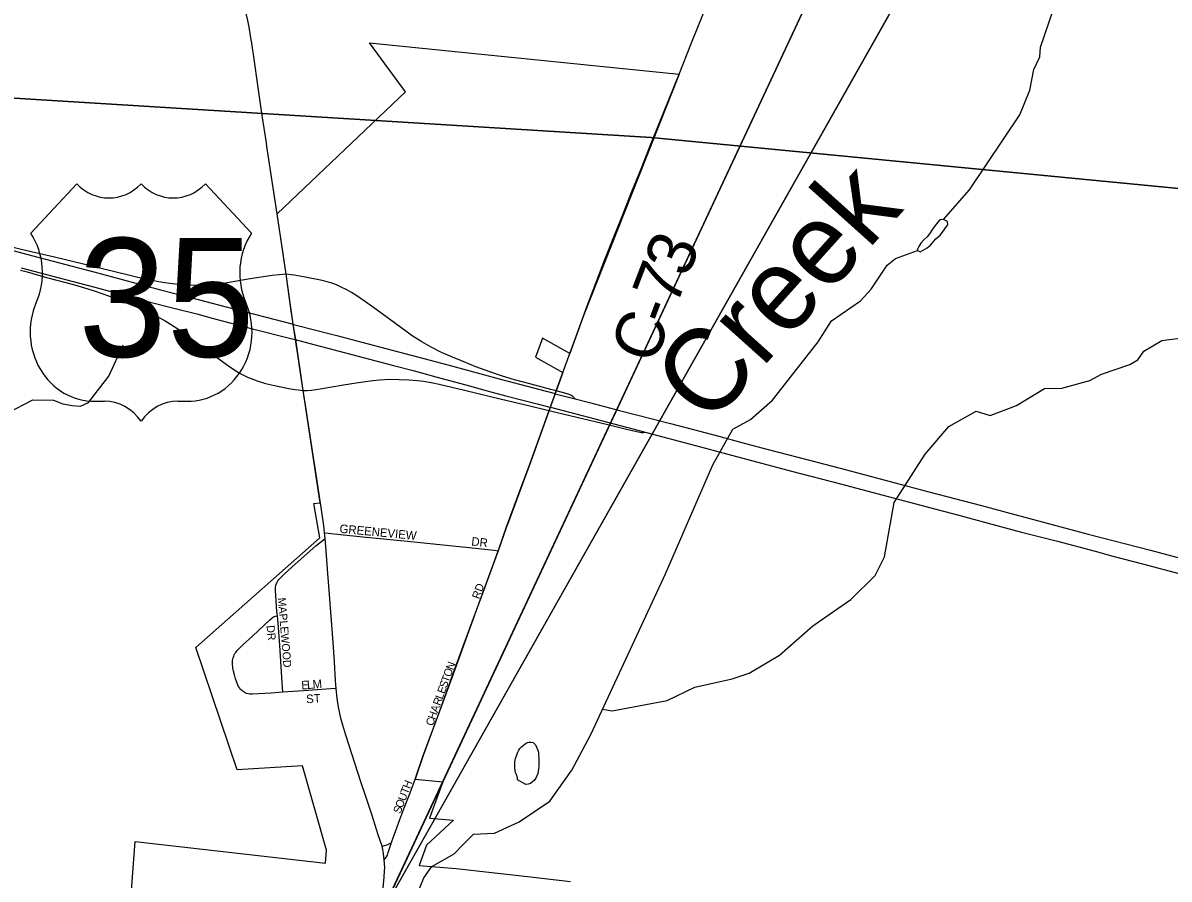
# Model space of a CAD drawing. Extents: x -13.9 to 69.1, y -25.2 to 26.1.
# Drawn here: x 3.861 to 5.08, y 17.993 to 18.903 of the extents above; entities that cross this region are included whole.
import ezdxf

# ---------------------------------------------------------------- set-up
doc = ezdxf.new("R2010")
doc.units = 0
for name, color, linetype in [('GM_X_City_Street', 7, 'Continuous'), ('GM_X_City_Street_Text', 7, 'Continuous'), ('GM_X_Corporation', 7, 'Continuous'), ('GM_X_County_Road', 7, 'Continuous'), ('GM_X_County_Road_Text', 7, 'Continuous'), ('GM_X_Interchange_Ramps', 7, 'Continuous'), ('GM_X_Major_River', 7, 'Continuous'), ('GM_X_Major_River_Text', 7, 'Continuous'), ('GM_X_Minor_Lake', 7, 'Continuous'), ('GM_X_Minor_River', 7, 'Continuous'), ('GM_X_State_Route', 7, 'Continuous'), ('GM_X_Township', 7, 'Continuous'), ('GM_X_US_Location', 7, 'Continuous'), ('GM_X_US_Route', 7, 'Continuous'), ('GM_X_US_Shield', 7, 'Continuous'), ('SH_Text', 7, 'Continuous')]:
    doc.layers.add(name, color=color, linetype=linetype)

msp = doc.modelspace()

# ---------------------------------------------------------------- linework, layer by layer
at = {"layer": 'GM_X_City_Street'}
for points in [[(4.1814, 18.3613), (4.1853, 18.3609), (4.2018, 18.3591), (4.2222, 18.357), (4.244, 18.3548), (4.2732, 18.3519), (4.3042, 18.3488), (4.3352, 18.3457), (4.3552, 18.3437), (4.3582, 18.3433), (4.3623, 18.3428), (4.3662, 18.3423)], [(4.3662, 18.3423), (4.3663, 18.3427), (4.3751, 18.3675)], [(4.1313, 18.2731), (4.1308, 18.2777), (4.1295, 18.2942), (4.1294, 18.3004), (4.1294, 18.3026), (4.1294, 18.304), (4.1296, 18.3051), (4.1301, 18.3065), (4.1308, 18.3081), (4.1314, 18.3094), (4.1319, 18.3102), (4.1329, 18.3115), (4.134, 18.3128), (4.1389, 18.3177), (4.1503, 18.328), (4.1723, 18.3476), (4.182, 18.3553)], [(4.3602, 18.3253), (4.3612, 18.3282), (4.3662, 18.3423)], [(4.2557, 18.0409), (4.2615, 18.0564), (4.2658, 18.0679), (4.2725, 18.0848), (4.2779, 18.0993), (4.2864, 18.1244), (4.3011, 18.1642), (4.318, 18.2106), (4.329, 18.2409), (4.3454, 18.2857), (4.3602, 18.3253)], [(4.1372, 18.1917), (4.1246, 18.1909), (4.1114, 18.19), (4.1044, 18.1897), (4.1022, 18.1898), (4.1003, 18.1901), (4.0986, 18.1906), (4.0972, 18.1912), (4.096, 18.1919), (4.0948, 18.1926), (4.0932, 18.194), (4.092, 18.1951), (4.091, 18.1964), (4.09, 18.198), (4.0892, 18.1998), (4.0885, 18.2014), (4.0869, 18.2061), (4.0857, 18.2101), (4.0846, 18.2143), (4.0843, 18.2155), (4.0839, 18.2172), (4.0838, 18.2187), (4.0836, 18.2209), (4.0836, 18.2231), (4.0837, 18.2255), (4.084, 18.227), (4.0843, 18.2284), (4.0849, 18.2302), (4.0855, 18.2316), (4.0862, 18.2329), (4.0871, 18.2342), (4.0883, 18.2358), (4.0897, 18.2373), (4.0946, 18.242), (4.1048, 18.2513), (4.1234, 18.2686), (4.1254, 18.2704), (4.1262, 18.2711), (4.1273, 18.2718), (4.1283, 18.2723), (4.1293, 18.2726), (4.1306, 18.273), (4.1313, 18.2731)], [(4.1372, 18.1917), (4.136, 18.2074), (4.1339, 18.2417), (4.132, 18.2653), (4.1313, 18.2731)], [(4.1939, 18.1959), (4.1929, 18.1958), (4.1736, 18.1945), (4.1592, 18.1934), (4.1425, 18.1921), (4.1372, 18.1917)], [(4.2527, 18.0319), (4.2551, 18.0391), (4.2557, 18.0409)], [(4.2427, 18.0281), (4.2465, 18.0292), (4.2487, 18.0299), (4.2508, 18.031), (4.2527, 18.0319)], [(4.245, 18.0134), (4.2474, 18.0169), (4.2484, 18.0186), (4.2493, 18.0212), (4.2527, 18.0319)]]:
    msp.add_lwpolyline(points, dxfattribs=at)
at = {"layer": 'GM_X_Corporation'}
msp.add_lwpolyline([(3.9756, 17.9719), (3.9802, 18.0329), (4.1826, 18.01), (4.1837, 18.024), (4.1579, 18.1136), (4.0885, 18.1093), (4.0447, 18.2393), (4.1764, 18.3558), (4.1701, 18.3926), (4.1767, 18.3932), (4.1588, 18.5125), (4.1508, 18.5667), (4.1482, 18.5832), (4.1405, 18.6363), (4.131, 18.7004), (4.2677, 18.8302), (4.2293, 18.8824), (4.5587, 18.8488), (4.4573, 18.5931), (4.4422, 18.5518), (4.4132, 18.5682), (4.4059, 18.5479), (4.4349, 18.5318), (4.4279, 18.5123), (4.4, 18.4353), (4.3771, 18.3731), (4.3751, 18.3675), (4.3662, 18.3423), (4.3496, 18.2969), (4.3439, 18.2816), (4.3167, 18.2071), (4.2864, 18.1244), (4.2779, 18.0993), (4.3074, 18.0965), (4.2932, 18.0578), (4.3186, 18.0556), (4.2898, 18.029), (4.282, 18.0075), (4.3216, 18.0042), (4.3973, 17.9958), (4.4431, 17.9907)], dxfattribs=at)
at = {"layer": 'GM_X_County_Road'}
for points in [[(4.5587, 18.8488), (4.5717, 18.8821), (4.5844, 18.9137), (4.6087, 18.9743), (4.6166, 18.9946), (4.623, 19.0123), (4.6292, 19.0308), (4.6346, 19.0483), (4.6407, 19.0699), (4.6483, 19.096), (4.6695, 19.1686), (4.6812, 19.2095), (4.6878, 19.2326)], [(4.5282, 18.7737), (4.5306, 18.7798), (4.5587, 18.8488)], [(4.5181, 18.7483), (4.5282, 18.7737)], [(4.4422, 18.5518), (4.4487, 18.5694), (4.4604, 18.6015), (4.4797, 18.652), (4.4892, 18.676), (4.4968, 18.6951), (4.5084, 18.7241), (4.5181, 18.7483)], [(4.4349, 18.5318), (4.4422, 18.5518)], [(4.3751, 18.3675), (4.3904, 18.4089), (4.3997, 18.4344), (4.4094, 18.461), (4.4203, 18.4914), (4.4216, 18.4949), (4.4228, 18.4982), (4.4268, 18.5092), (4.4278, 18.5121), (4.4349, 18.5318)]]:
    msp.add_lwpolyline(points, dxfattribs=at)
at = {"layer": 'GM_X_Interchange_Ramps'}
for points in [[(4.1405, 18.6363), (4.1259, 18.6349), (4.1023, 18.6314), (4.0762, 18.6269), (4.0691, 18.6259), (4.0611, 18.625), (4.0537, 18.6247), (4.0432, 18.6243), (4.0305, 18.6249), (4.0193, 18.6261), (4.0093, 18.6273), (4.0018, 18.6288), (3.9919, 18.6308), (3.925, 18.647), (3.8942, 18.6543), (3.865, 18.6611), (3.8369, 18.6678), (3.8164, 18.6728), (3.811, 18.674), (3.8075, 18.6745), (3.8057, 18.6745), (3.8028, 18.6738)], [(3.8583, 18.6407), (3.8653, 18.6386), (3.8857, 18.6329), (3.913, 18.6256), (3.9253, 18.622), (3.9364, 18.6185), (3.9528, 18.6128), (3.9689, 18.6067), (3.9829, 18.601), (3.9951, 18.5956), (4.0017, 18.5923), (4.012, 18.5867), (4.0244, 18.5789), (4.0383, 18.569), (4.0651, 18.549), (4.0742, 18.5424), (4.083, 18.5362), (4.0912, 18.5312), (4.0946, 18.5294), (4.0995, 18.5269), (4.1052, 18.5245), (4.11, 18.5228), (4.1186, 18.5202), (4.1283, 18.5179), (4.1435, 18.5149), (4.15, 18.5138), (4.1538, 18.5132), (4.1588, 18.5125)], [(4.4481, 18.5037), (4.4466, 18.5052), (4.4456, 18.5062), (4.4433, 18.5076), (4.4407, 18.5087), (4.4371, 18.5098), (4.4278, 18.5121), (4.4265, 18.5125), (4.4222, 18.5135), (4.3997, 18.5196), (4.3836, 18.5239), (4.3708, 18.5278), (4.3571, 18.5325), (4.3424, 18.5379), (4.3289, 18.5433), (4.3176, 18.5479), (4.3058, 18.5531), (4.2948, 18.5587), (4.285, 18.5642), (4.2746, 18.5709), (4.2625, 18.5795), (4.2375, 18.598), (4.225, 18.6068), (4.2147, 18.6141), (4.2101, 18.6168), (4.2052, 18.6197), (4.1992, 18.6226), (4.1942, 18.6248), (4.1892, 18.6266), (4.1843, 18.6281), (4.1771, 18.63), (4.1609, 18.6332), (4.1493, 18.6353), (4.1461, 18.6356), (4.1405, 18.6363)], [(4.1588, 18.5125), (4.1629, 18.5125), (4.1675, 18.5128), (4.1768, 18.5143), (4.2018, 18.5188), (4.215, 18.5209), (4.225, 18.5223), (4.2327, 18.5234), (4.2402, 18.5241), (4.2504, 18.5245), (4.261, 18.5244), (4.2712, 18.5241), (4.2801, 18.5233), (4.2869, 18.5224), (4.2966, 18.5208), (4.3034, 18.5194), (4.3302, 18.5131), (4.3695, 18.5034), (4.3982, 18.4966), (4.4186, 18.4918), (4.4203, 18.4914), (4.4275, 18.4897), (4.4498, 18.4843), (4.4826, 18.4764), (4.5056, 18.4707), (4.5152, 18.4685), (4.5181, 18.4679), (4.5195, 18.4678), (4.5208, 18.4679), (4.5225, 18.4683)]]:
    msp.add_lwpolyline(points, dxfattribs=at)
at = {"layer": 'GM_X_Major_River'}
for points in [[(4.8397, 18.6945), (4.8672, 18.7259), (4.9208, 18.8058), (4.9317, 18.8321), (4.9358, 18.8538), (4.9422, 18.8675), (4.943, 18.8776), (4.9565, 18.917), (4.9627, 18.975), (4.9726, 19.0006), (4.9871, 19.0239), (5.0063, 19.0406), (5.0165, 19.0476), (5.0544, 19.0602), (5.0714, 19.0839), (5.0917, 19.0918), (5.1025, 19.0934), (5.124, 19.0911), (5.1581, 19.0773), (5.1695, 19.0737), (5.2352, 19.0599), (5.2439, 19.0561), (5.28, 19.027)], [(4.8397, 18.6945), (4.8359, 18.6942), (4.8318, 18.6896), (4.828, 18.6842), (4.8249, 18.6792), (4.8225, 18.676), (4.8191, 18.6732), (4.8156, 18.6692), (4.8135, 18.6656), (4.8125, 18.6635), (4.8118, 18.6617), (4.8148, 18.6602), (4.8223, 18.6644), (4.826, 18.6672), (4.8315, 18.674), (4.836, 18.6779), (4.8398, 18.6822), (4.8418, 18.6857), (4.8443, 18.6886), (4.844, 18.6922)], [(4.844, 18.6922), (4.8397, 18.6945)], [(4.2684, 17.9482), (4.2871, 17.9943), (4.2954, 18.0065), (4.3192, 18.0198), (4.3292, 18.0301), (4.3398, 18.0408), (4.3621, 18.0421), (4.3885, 18.0539), (4.4209, 18.076), (4.4444, 18.109), (4.4646, 18.147), (4.5439, 18.3175), (4.5945, 18.4335), (4.6157, 18.4715), (4.6344, 18.4816), (4.6577, 18.5022), (4.7063, 18.5644), (4.7205, 18.5866), (4.7515, 18.6081), (4.7629, 18.6202), (4.7799, 18.646), (4.7887, 18.6531), (4.8122, 18.6615)]]:
    msp.add_lwpolyline(points, dxfattribs=at)
at = {"layer": 'GM_X_Minor_Lake'}
for points in [[(4.8397, 18.6945), (4.8672, 18.7259), (4.9208, 18.8058), (4.9317, 18.8321), (4.9358, 18.8538), (4.9422, 18.8675), (4.943, 18.8776), (4.9565, 18.917), (4.9627, 18.975), (4.9726, 19.0006), (4.9871, 19.0239), (5.0063, 19.0406), (5.0165, 19.0476), (5.0544, 19.0602), (5.0714, 19.0839), (5.0917, 19.0918), (5.1025, 19.0934), (5.124, 19.0911), (5.1581, 19.0773), (5.1695, 19.0737), (5.2352, 19.0599), (5.2439, 19.0561), (5.28, 19.027)], [(4.3866, 18.0985), (4.3866, 18.1007), (4.3856, 18.1043), (4.3846, 18.1065), (4.3843, 18.1083), (4.384, 18.1113), (4.3837, 18.1134), (4.3837, 18.116), (4.3837, 18.1178), (4.3844, 18.1214), (4.3855, 18.124), (4.3868, 18.1272), (4.3882, 18.1301), (4.3893, 18.1319), (4.391, 18.1337), (4.393, 18.1355), (4.3947, 18.1369), (4.3971, 18.1384), (4.3991, 18.1387), (4.4011, 18.1387), (4.4035, 18.1383), (4.4058, 18.1357), (4.4078, 18.131), (4.4085, 18.1291), (4.4091, 18.1273), (4.4091, 18.1248), (4.4094, 18.1222), (4.4094, 18.1182), (4.4093, 18.1131), (4.409, 18.1102), (4.4086, 18.1077), (4.4082, 18.1055), (4.4072, 18.103), (4.4062, 18.1004), (4.4044, 18.0979), (4.4027, 18.0965), (4.4004, 18.0947), (4.398, 18.094), (4.3956, 18.0937), (4.3866, 18.0985)]]:
    msp.add_lwpolyline(points, dxfattribs=at)
at = {"layer": 'GM_X_Minor_River'}
for points in [[(4.477, 18.1737), (4.4873, 18.1719), (4.5459, 18.1831), (4.5751, 18.1971), (4.615, 18.2061), (4.633, 18.2119), (4.6653, 18.2313), (4.7009, 18.2622), (4.7411, 18.2905), (4.7672, 18.3158), (4.777, 18.3356), (4.7874, 18.3936), (4.8202, 18.4449), (4.8453, 18.4743), (4.8743, 18.4908), (4.8893, 18.4861), (4.9175, 18.4965), (4.9471, 18.5148), (4.9657, 18.5152), (4.9955, 18.5233), (5.0077, 18.53), (5.0379, 18.5403), (5.0464, 18.5452), (5.0526, 18.5546), (5.072, 18.5658), (5.091, 18.5684)], [(3.5115, 18.2665), (3.5395, 18.3003), (3.5501, 18.3328), (3.5754, 18.3741), (3.5933, 18.3945), (3.6103, 18.4025), (3.6197, 18.4041), (3.6603, 18.4302), (3.688, 18.4384), (3.7218, 18.4381), (3.7576, 18.4436), (3.7769, 18.4494), (3.8245, 18.4735), (3.844, 18.4884), (3.8712, 18.5028), (3.8931, 18.5024), (3.9031, 18.4985), (3.9132, 18.4965), (3.922, 18.496), (3.9304, 18.4998), (3.9521, 18.5278), (3.9672, 18.5613)]]:
    msp.add_lwpolyline(points, dxfattribs=at)
at = {"layer": 'GM_X_State_Route'}
for points in [[(4.1041, 18.8819), (4.1035, 18.8855), (4.1013, 18.899), (4.0995, 18.9078), (4.0968, 18.9187), (4.0947, 18.9262), (4.0894, 18.9425), (4.0793, 18.9717)], [(4.1526, 18.5531), (4.1517, 18.5593), (4.1506, 18.5667), (4.1482, 18.583), (4.1457, 18.5999), (4.1405, 18.6363), (4.1371, 18.6604), (4.1352, 18.6721), (4.131, 18.7004), (4.1201, 18.7722), (4.1196, 18.7758), (4.1151, 18.805), (4.1105, 18.8373), (4.1066, 18.865), (4.1041, 18.8819)], [(4.1814, 18.3613), (4.181, 18.3658), (4.1801, 18.3741), (4.1724, 18.4233), (4.168, 18.4532), (4.1615, 18.4948), (4.1588, 18.5125), (4.1567, 18.5265), (4.1526, 18.5531)], [(4.1829, 18.3468), (4.1825, 18.3508), (4.182, 18.3553), (4.1814, 18.3613)], [(4.2447, 18.0163), (4.2443, 18.0203), (4.2435, 18.0245), (4.2427, 18.0281), (4.2385, 18.0403), (4.2368, 18.0458), (4.2322, 18.0606), (4.2253, 18.081), (4.2206, 18.0954), (4.2041, 18.1462), (4.2009, 18.1567), (4.1993, 18.1629), (4.1978, 18.169), (4.1964, 18.1758), (4.1949, 18.1855), (4.1939, 18.1954), (4.1939, 18.1959), (4.1932, 18.2044), (4.1919, 18.2241), (4.1905, 18.2447), (4.1891, 18.2636), (4.1888, 18.2682), (4.1883, 18.2768), (4.1868, 18.2956), (4.1851, 18.3181), (4.1837, 18.3371), (4.1829, 18.3468)], [(4.2284, 17.8235), (4.2286, 17.826), (4.2319, 17.8613), (4.2342, 17.8848), (4.2436, 17.9795), (4.245, 17.9952), (4.2454, 18.002), (4.2456, 18.0054), (4.245, 18.0134), (4.2447, 18.0163)]]:
    msp.add_lwpolyline(points, dxfattribs=at)
at = {"layer": 'GM_X_Township'}
msp.add_lwpolyline([(8.0976, 21.2145), (2.668, 21.2145), (2.5713, 21.1249), (2.5376, 21.0933), (2.5207, 21.0774), (2.9282, 20.5283), (2.3149, 19.9943), (2.3345, 19.9924), (2.4186, 19.989), (2.4692, 19.987), (2.5176, 19.987), (2.5995, 20.0118), (2.5714, 18.9023), (4.5288, 18.7816), (7.8661, 18.459), (7.9988, 20.0382), (8.0428, 20.5625)], close=True, dxfattribs=at)
msp.add_lwpolyline([(7.8661, 18.459), (4.5288, 18.7816), (2.5714, 18.9023), (2.2304, 17.2467), (2.1794, 16.5325), (2.1711, 16.462), (2.216, 16.457), (2.2023, 16.145)], dxfattribs=at)
at = {"layer": 'GM_X_US_Route'}
for points in [[(3.8154, 18.6705), (3.8713, 18.6558), (3.9416, 18.6372), (4.0071, 18.6198), (4.0404, 18.6111), (4.0769, 18.6015), (4.1482, 18.583), (4.15, 18.5826), (4.1721, 18.5767), (4.1847, 18.5735), (4.1944, 18.571), (4.2212, 18.564), (4.2347, 18.5605), (4.3125, 18.5398), (4.3672, 18.525), (4.4254, 18.5096), (4.4268, 18.5092), (4.4481, 18.5037), (4.4633, 18.4998), (4.4951, 18.4912), (4.5493, 18.4774), (4.6008, 18.4639), (4.6239, 18.4578), (4.6534, 18.45), (4.7055, 18.4363), (4.7367, 18.4282), (4.8027, 18.4106), (4.8241, 18.4049), (4.88, 18.3902), (4.9154, 18.3807), (4.9937, 18.36), (5.0598, 18.3427), (5.1403, 18.3212)], [(3.8587, 18.6431), (3.9059, 18.6306), (3.9424, 18.621), (3.9826, 18.6102), (3.996, 18.6067), (4.0213, 18.6003), (4.0455, 18.5941), (4.0621, 18.5896), (4.105, 18.5781), (4.1458, 18.5679)], [(4.1458, 18.5679), (4.1506, 18.5667), (4.1528, 18.5662)], [(4.1528, 18.5662), (4.2548, 18.5392), (4.2757, 18.5337), (4.2998, 18.5273), (4.3357, 18.5175), (4.3544, 18.5124), (4.3742, 18.5071), (4.4075, 18.4986), (4.4197, 18.4954)], [(4.4197, 18.4954), (4.4216, 18.4949), (4.5159, 18.47), (4.5225, 18.4683), (4.576, 18.454), (4.6104, 18.445), (4.6779, 18.4269), (4.73, 18.4132), (4.8261, 18.3878), (4.8545, 18.3803), (4.8873, 18.3715), (4.9227, 18.3621), (4.9609, 18.3523), (5.0011, 18.3416), (5.0199, 18.3366), (5.0515, 18.3282), (5.0913, 18.3178)]]:
    msp.add_lwpolyline(points, dxfattribs=at)
at = {"layer": 'GM_X_US_Shield'}
for p, q in [((3.918, 18.7324), (3.8691, 18.6798)), ((4.1037, 18.6798), (4.0548, 18.7324)), ((3.9375, 18.5011), (3.9473, 18.5011)), ((4.0255, 18.5011), (4.0353, 18.5011))]:
    msp.add_line(p, q, dxfattribs=at)
for centre, major_axis, start_param, end_param in [((3.9522, 18.77), (0, -0.0526), 5.507788, 7.058583), ((4.0206, 18.77), (0, -0.0526), 5.507788, 7.058583), ((3.8131, 18.6376), (0, 0.0736), 4.268152, 5.32327), ((4.1597, 18.6376), (0, -0.0736), 4.101508, 5.156625), ((3.9368, 18.5747), (0, -0.0736), 4.273123, 6.294325), ((4.036, 18.5747), (0, -0.0736), 6.272046, 8.293248), ((3.9473, 18.4485), (0, 0.0526), 5.35589, 6.283185), ((4.0255, 18.4485), (0, 0.0526), 0, 0.927295)]:
    msp.add_ellipse(centre, major_axis=major_axis, ratio=0.929448, start_param=start_param, end_param=end_param, dxfattribs=at)
at = {"layer": 'SH_Text'}
for p, q in [((4.2413, 17.9556), (5.0073, 19.5943)), ((5.0073, 19.3117), (4.2413, 17.9556))]:
    msp.add_line(p, q, dxfattribs=at)
msp.add_lwpolyline([(5.0073, 19.5943), (4.2413, 17.9556), (5.0073, 19.3117)], close=True, dxfattribs=at)

# ---------------------------------------------------------------- texts
at = {"layer": 'GM_X_City_Street_Text'}
for s, height, rotation, p in [('GREENEVIEW', 0.00906, 354.5976, (4.1971, 18.3614)), ('DR', 0.00906, 353.5424, (4.3372, 18.3479)), ('RD', 0.00851, 70.1253, (4.346, 18.2902)), ('MAPLEWOOD', 0.00843, 274.722, (4.1318, 18.292)), ('DR', 0.00843, 275.5845, (4.1198, 18.2626)), ('N', 0.00851, 69.9326, (4.3182, 18.2147)), ('T', 0.00851, 69.9374, (4.3133, 18.2014)), ('O', 0.00851, 69.9543, (4.3155, 18.2073)), ('E', 0.00906, 3.2348, (4.157, 18.1947)), ('L', 0.00906, 4.6068, (4.1632, 18.1951)), ('M', 0.00906, 4.7193, (4.1691, 18.1956)), ('E', 0.00851, 69.9374, (4.309, 18.1895)), ('S', 0.00851, 69.9374, (4.3111, 18.1954)), ('ST', 0.00906, 3.8452, (4.1622, 18.18)), ('R', 0.00851, 69.9347, (4.3044, 18.1769)), ('L', 0.00851, 69.9374, (4.3068, 18.1836)), ('A', 0.00851, 69.9979, (4.3017, 18.1695)), ('C', 0.00849, 72.6704, (4.297, 18.1553)), ('H', 0.0085, 71.0576, (4.2991, 18.162)), ('T', 0.00852, 68.8221, (4.2699, 18.0826)), ('H', 0.00852, 68.8173, (4.2722, 18.0885)), ('O', 0.00852, 69.2637, (4.2643, 18.0679)), ('U', 0.00852, 68.8365, (4.2671, 18.0753)), ('S', 0.00851, 70.4367, (4.2622, 18.062))]:
    msp.add_text(s, height=height, rotation=rotation, dxfattribs=at).set_placement(p)
at = {"layer": 'GM_X_County_Road_Text'}
for s, height, rotation, p in [('3', 0.0512, 68.007, (4.5671, 18.6314)), ('7', 0.0511, 68.9987, (4.5553, 18.6007)), ('-', 0.0511, 69.2378, (4.5475, 18.5801)), ('C', 0.0511, 69.3072, (4.5319, 18.5387))]:
    msp.add_text(s, height=height, rotation=rotation, dxfattribs=at).set_placement(p)
at = {"layer": 'GM_X_Major_River_Text'}
msp.add_text('Creek', height=0.08738, rotation=48.1064, dxfattribs=at).set_placement((4.5901, 18.4729))
at = {"layer": 'GM_X_US_Location'}
for s in ['/', '0']:
    msp.add_text(s, height=0.000181, dxfattribs=at).set_placement((3.9863, 18.6105))
msp.add_text('35', height=0.000181, rotation=0, dxfattribs=at).set_placement((3.9516, 18.573))
at = {"layer": 'GM_X_US_Shield'}
msp.add_text('35', height=0.12619, dxfattribs=at).set_placement((3.9196, 18.5484))

doc.saveas('drawing.dxf')
